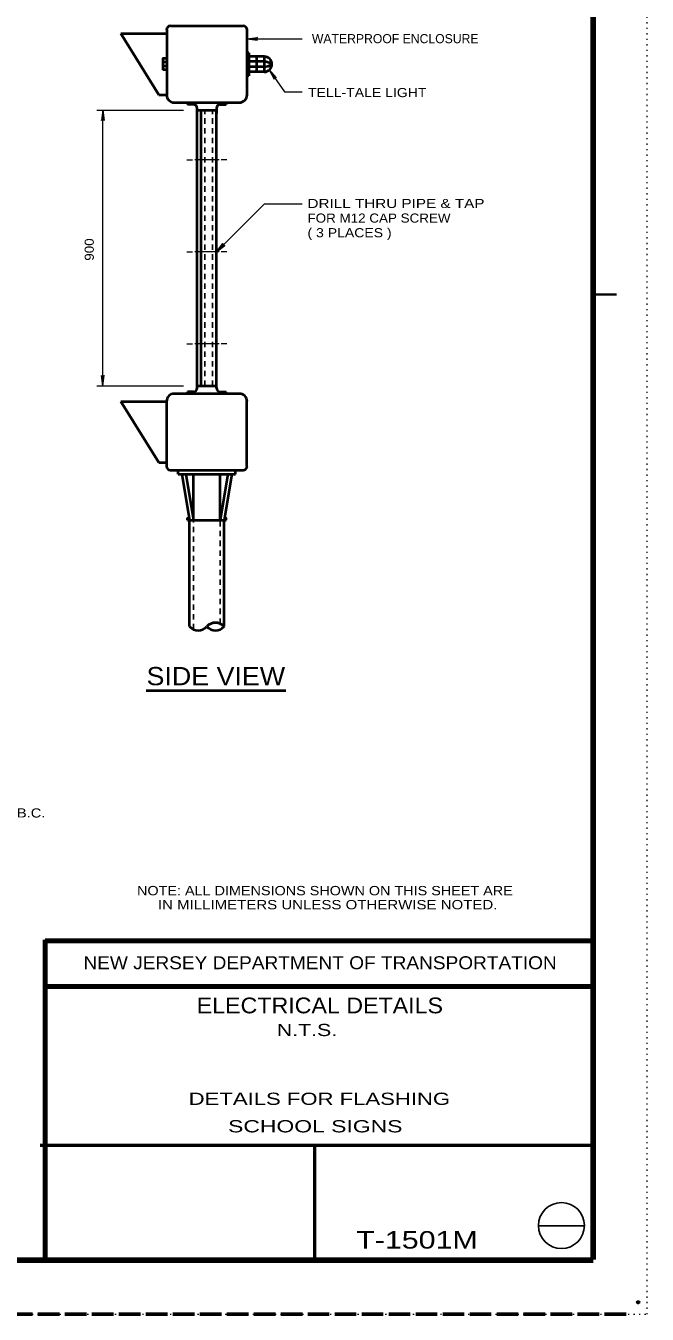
# Model space of a CAD drawing. Extents: x 312583 to 312854, y 144419 to 144597.
# Drawn here: x 312801.7 to 312853.5, y 144418.6 to 144526 of the extents above; entities that cross this region are included whole.
import ezdxf
from ezdxf.enums import TextEntityAlignment as Align

# ---------------------------------------------------------------- set-up
doc = ezdxf.new("R2010")
doc.units = 0
doc.header["$LTSCALE"] = 0.3
doc.header["$PDMODE"] = 32
doc.header["$PDSIZE"] = 0.15
for name, pattern in [('DOTTED', [1.5, 0.3, -1.2]), ('LONG_DASHED', [7.5, 6, -1.5]), ('SHORT_DASHED', [2.7, 1.5, -1.2])]:
    doc.linetypes.add(name, pattern=pattern)
for name, color, linetype, lineweight in [('1', 7, 'Continuous', 40), ('10', 7, 'Continuous', 25), ('2', 7, 'Continuous', 13), ('62', 7, 'DOTTED', 13), ('63', 7, 'LONG_DASHED', 60)]:
    doc.layers.add(name, color=color, linetype=linetype, lineweight=lineweight)

msp = doc.modelspace()

# ---------------------------------------------------------------- linework, layer by layer
at = {"layer": '1', "lineweight": 158}
for p, q in [((312849, 144423.1446), (312849, 144585.0846)), ((312616.5, 144423.0846), (312849, 144423.0846))]:
    msp.add_line(p, q, dxfattribs=at)
at = {"layer": '1'}
for p, q in [((312809.6087, 144525.3719), (312813.442, 144525.3719)), ((312812.798, 144520.2659), (312809.6087, 144525.3719)), ((312813.442, 144525.6939), (312813.442, 144520.2659)), ((312813.7563, 144526.0159), (312819.8207, 144526.0159)), ((312820.135, 144525.6939), (312820.135, 144520.2659)), ((312813.442, 144522.9799), (312813.12, 144522.9799)), ((312820.296, 144523.7773), (312820.135, 144523.7773)), ((312820.296, 144523.7773), (312820.296, 144521.8606)), ((312821.5763, 144523.4553), (312820.296, 144523.4553)), ((312821.5763, 144523.0336), (312820.296, 144523.0336)), ((312820.94, 144523.4553), (312820.94, 144522.1826)), ((312821.5763, 144523.4553), (312821.5763, 144522.1826)), ((312813.442, 144522.6579), (312813.12, 144522.6579)), ((312813.442, 144522.3359), (312813.12, 144522.3359)), ((312820.296, 144521.8606), (312820.135, 144521.8606)), ((312821.5763, 144522.6043), (312820.296, 144522.6043)), ((312821.5763, 144522.1826), (312820.296, 144522.1826)), ((312812.798, 144520.2659), (312813.442, 144520.2659)), ((312814.0783, 144519.6219), (312819.4987, 144519.6219)), ((312815.19, 144519.6219), (312815.19, 144519.4609)), ((312815.673, 144519.4609), (312815.19, 144519.4609)), ((312815.9873, 144495.9856), (312815.9873, 144519.1466)), ((312815.9873, 144518.9856), (312817.5897, 144518.9856)), ((312816.3093, 144495.9856), (312816.3093, 144518.9856)), ((312817.5897, 144519.1466), (312817.5897, 144518.7096)), ((312817.5897, 144495.9856), (312817.5897, 144518.9856)), ((312817.904, 144519.4609), (312818.387, 144519.4609)), ((312818.387, 144519.6219), (312818.387, 144519.4609)), ((312814.0783, 144495.3493), (312819.4987, 144495.3493)), ((312815.673, 144495.5026), (312815.19, 144495.5026)), ((312815.19, 144495.3493), (312815.19, 144495.5026)), ((312815.9873, 144495.8246), (312815.9873, 144495.9856)), ((312815.9873, 144495.9856), (312817.5897, 144495.9856)), ((312817.5897, 144495.8246), (312817.5897, 144495.9856)), ((312817.904, 144495.5026), (312818.387, 144495.5026)), ((312818.387, 144495.3493), (312818.387, 144495.5026)), ((312809.6087, 144494.7053), (312813.442, 144494.7053)), ((312812.798, 144489.5993), (312809.6087, 144494.7053)), ((312813.442, 144489.2773), (312813.442, 144494.7053)), ((312820.135, 144489.2773), (312820.135, 144494.7053)), ((312812.798, 144489.5993), (312813.442, 144489.5993)), ((312813.7563, 144488.9553), (312819.8207, 144488.9553)), ((312814.4003, 144488.6409), (312814.4003, 144488.9553)), ((312814.4003, 144488.6409), (312819.1767, 144488.6409)), ((312814.707, 144488.6409), (312815.3433, 144484.7999)), ((312815.029, 144488.6409), (312815.673, 144484.8076)), ((312815.673, 144484.8076), (312815.673, 144488.6409)), ((312817.904, 144484.8076), (312817.904, 144488.6409)), ((312817.904, 144484.8076), (312817.904, 144488.6409)), ((312818.548, 144488.6409), (312817.904, 144484.8076)), ((312818.87, 144488.6409), (312818.226, 144484.7999)), ((312819.1767, 144488.6409), (312819.1767, 144488.9553)), ((312815.19, 144484.8076), (312818.387, 144484.8076)), ((312815.351, 144475.9296), (312815.351, 144484.8076)), ((312818.226, 144475.9296), (312818.226, 144484.8076))]:
    msp.add_line(p, q, dxfattribs=at)
at = {"layer": '1', "linetype": 'SHORT_DASHED', "lineweight": 25}
for p, q in [((312816.6313, 144495.9856), (312816.6313, 144518.9856)), ((312817.2677, 144495.9856), (312817.2677, 144518.9856)), ((312815.673, 144475.6996), (312815.673, 144484.8076)), ((312817.904, 144476.1596), (312817.904, 144484.8076))]:
    msp.add_line(p, q, dxfattribs=at)
at = {"layer": '1', "lineweight": 35}
msp.add_line((312849, 144503.6216), (312850.932, 144503.6216), dxfattribs=at)
at = {"layer": '1', "lineweight": 80}
for p, q in [((312803.31, 144423.1446), (312803.31, 144449.8146)), ((312803.31, 144449.7246), (312849, 144449.7246)), ((312803.31, 144445.9146), (312849, 144445.9146))]:
    msp.add_line(p, q, dxfattribs=at)
at = {"layer": '1', "lineweight": 53}
for p, q in [((312849, 144432.6666), (312802.885, 144432.6666)), ((312825.7547, 144432.6666), (312825.7547, 144423.1446))]:
    msp.add_line(p, q, dxfattribs=at)
at = {"layer": '1'}
for points in [[(312813.442, 144523.2943), (312813.12, 144523.2943), (312813.12, 144522.3359)], [(312815.19, 144484.8076), (312815.19, 144484.9609), (312815.3203, 144484.9609)], [(312818.387, 144484.8076), (312818.387, 144484.9609), (312818.2567, 144484.9609)]]:
    msp.add_lwpolyline(points, dxfattribs=at)
for centre, radius, start, end in [((312813.7576, 144525.6927), 0.3194, 90, 180), ((312819.8181, 144525.6927), 0.3194, 0, 90), ((312821.5751, 144522.8177), 0.6389, 270, 90), ((312821.5022, 144521.7421), 1.2897, 56.50579, 86.76188), ((312821.5022, 144523.8919), 1.2897, 273.23812, 303.49421), ((312814.0771, 144520.2621), 0.6389, 180, 270), ((312819.4987, 144520.2621), 0.6389, 270, 0), ((312815.6698, 144519.144), 0.3194, 0, 90), ((312817.9059, 144519.144), 0.3194, 90, 180), ((312814.0771, 144494.7065), 0.6389, 90, 180), ((312815.6698, 144495.8246), 0.3194, 270, 0), ((312817.9059, 144495.8246), 0.3194, 180, 270), ((312819.4987, 144494.7065), 0.6389, 0, 90), ((312813.7576, 144489.276), 0.3194, 180, 270), ((312819.8181, 144489.276), 0.3194, 270, 0), ((312816.0691, 144476.5778), 0.9683, 222.07502, 317.92498), ((312817.5066, 144475.2801), 0.9683, 42.07502, 137.92498), ((312817.5066, 144476.5778), 0.9683, 222.07502, 317.92498)]:
    msp.add_arc(centre, radius, start, end, dxfattribs=at)
msp.add_point((312852.75, 144419.5846), dxfattribs=at)
at = {"layer": '10'}
msp.add_line((312844.4383, 144425.966), (312848.2793, 144425.966), dxfattribs=at)
msp.add_circle((312846.3494, 144425.9805), 1.9159, dxfattribs=at)
at = {"layer": '2'}
for p, q in [((312820.135, 144524.9426), (312821.0013, 144525.0499)), ((312821.0013, 144525.0499), (312820.7253, 144524.9426)), ((312820.135, 144524.9426), (312824.7273, 144524.9426)), ((312820.135, 144524.9426), (312821.0013, 144524.8353)), ((312821.0013, 144524.8353), (312820.7253, 144524.9426)), ((312821.998, 144522.3436), (312823.2553, 144520.5113)), ((312821.998, 144522.3436), (312822.4043, 144521.5693)), ((312821.998, 144522.3436), (312822.5807, 144521.6843)), ((312822.4043, 144521.5693), (312822.3353, 144521.8529)), ((312822.5807, 144521.6843), (312822.3353, 144521.8529)), ((312823.2553, 144520.5113), (312824.7273, 144520.5113)), ((312807.6307, 144518.9856), (312814.845, 144518.9856)), ((312808.129, 144518.9856), (312808.0217, 144518.1193)), ((312808.129, 144495.9856), (312808.129, 144518.9856)), ((312808.129, 144518.9856), (312808.2363, 144518.1193)), ((312808.0217, 144518.1193), (312808.129, 144518.3953)), ((312808.2363, 144518.1193), (312808.129, 144518.3953)), ((312815.1133, 144514.8303), (312815.604, 144514.8303)), ((312817.812, 144514.8303), (312815.7803, 144514.8303)), ((312818.4637, 144514.8303), (312817.9883, 144514.8303)), ((312817.5973, 144507.1713), (312821.5993, 144511.1809)), ((312821.5993, 144511.1809), (312824.735, 144511.1809)), ((312817.5973, 144507.1713), (312818.134, 144507.8536)), ((312818.134, 144507.8536), (312818.019, 144507.5853)), ((312815.1133, 144507.1636), (312815.604, 144507.1636)), ((312817.812, 144507.1636), (312815.7803, 144507.1636)), ((312817.5973, 144507.1713), (312818.2873, 144507.7079)), ((312818.4637, 144507.1636), (312817.9883, 144507.1636)), ((312818.2873, 144507.7079), (312818.019, 144507.5853)), ((312815.1133, 144499.4969), (312815.604, 144499.4969)), ((312817.812, 144499.4969), (312815.7803, 144499.4969)), ((312818.4637, 144499.4969), (312817.9883, 144499.4969)), ((312808.0217, 144496.8519), (312808.129, 144496.5759)), ((312808.129, 144495.9856), (312808.0217, 144496.8519)), ((312808.2363, 144496.8519), (312808.129, 144496.5759)), ((312808.129, 144495.9856), (312808.2363, 144496.8519)), ((312807.6307, 144495.9856), (312814.845, 144495.9856))]:
    msp.add_line(p, q, dxfattribs=at)
at = {"layer": '2', "lineweight": 40}
msp.add_line((312811.7438, 144470.5859), (312823.3661, 144470.5859), dxfattribs=at)
at = {"layer": '62'}
msp.add_lwpolyline([(312601.2, 144418.5846), (312853.5, 144418.5846), (312853.5, 144596.7846)], dxfattribs=at)
at = {"layer": '63'}
msp.add_line((312851.75, 144418.5846), (312583.526, 144418.5846), dxfattribs=at)

# ---------------------------------------------------------------- texts
at = {"layer": '1'}
for s, width, p in [('NOTE: ALL DIMENSIONS SHOWN ON THIS SHEET ARE', 1.15, (312810.9698, 144453.5167)), ('     IN MILLIMETERS UNLESS OTHERWISE NOTED.', 1.2, (312810.9697, 144452.3467))]:
    msp.add_text(s, height=0.78, dxfattribs=dict(at, width=width)).set_placement(p)
for s, height, width, p in [('NEW JERSEY DEPARTMENT OF TRANSPORTATION', 1.08, 1.1, (312826.2285, 144447.3546)), ('ELECTRICAL DETAILS', 1.315, 1.1, (312826.2109, 144443.6759)), ('T-1501M   ', 1.457, 1.3, (312835.3614, 144424.0569))]:
    msp.add_text(s, height=height, dxfattribs=dict(at, width=width)).set_placement(p, align=Align.CENTER)
at = {"layer": '2'}
msp.add_text('WATERPROOF ENCLOSURE', height=0.76, dxfattribs=at).set_placement((312825.5479, 144524.5698))
for s, width, p in [('TELL-TALE LIGHT', 1.15, (312825.2233, 144520.0732)), ('DRILL THRU PIPE & TAP', 1.25, (312825.1797, 144510.8273)), ('FOR M12 CAP SCREW', 1.1, (312825.1797, 144509.6073)), ('( 3 PLACES )', 1.15, (312825.1797, 144508.3873)), ('SIGN FOUNDATION 267 MM  B.C.', 1.2, (312784.1526, 144460.0049))]:
    msp.add_text(s, height=0.76, dxfattribs=dict(at, width=width)).set_placement(p)
at = {"layer": '2', "width": 1.1}
msp.add_text('900', height=0.76, rotation=90, dxfattribs=at).set_placement((312807.366, 144506.4315))
at = {"layer": '2'}
for s, height, width, p in [('SIDE VIEW', 1.52, 1.1, (312817.5393, 144471.0326)), ('    N.T.S.  ', 1.02, 1.3, (312824.6461, 144441.778)), ('             DETAILS FOR FLASHING            ', 1.02, 1.35, (312825.9156, 144436.0399)), ('                SCHOOL SIGNS                ', 1.02, 1.4, (312825.8274, 144433.7476))]:
    msp.add_text(s, height=height, dxfattribs=dict(at, width=width)).set_placement(p, align=Align.CENTER)

doc.saveas('drawing.dxf')
